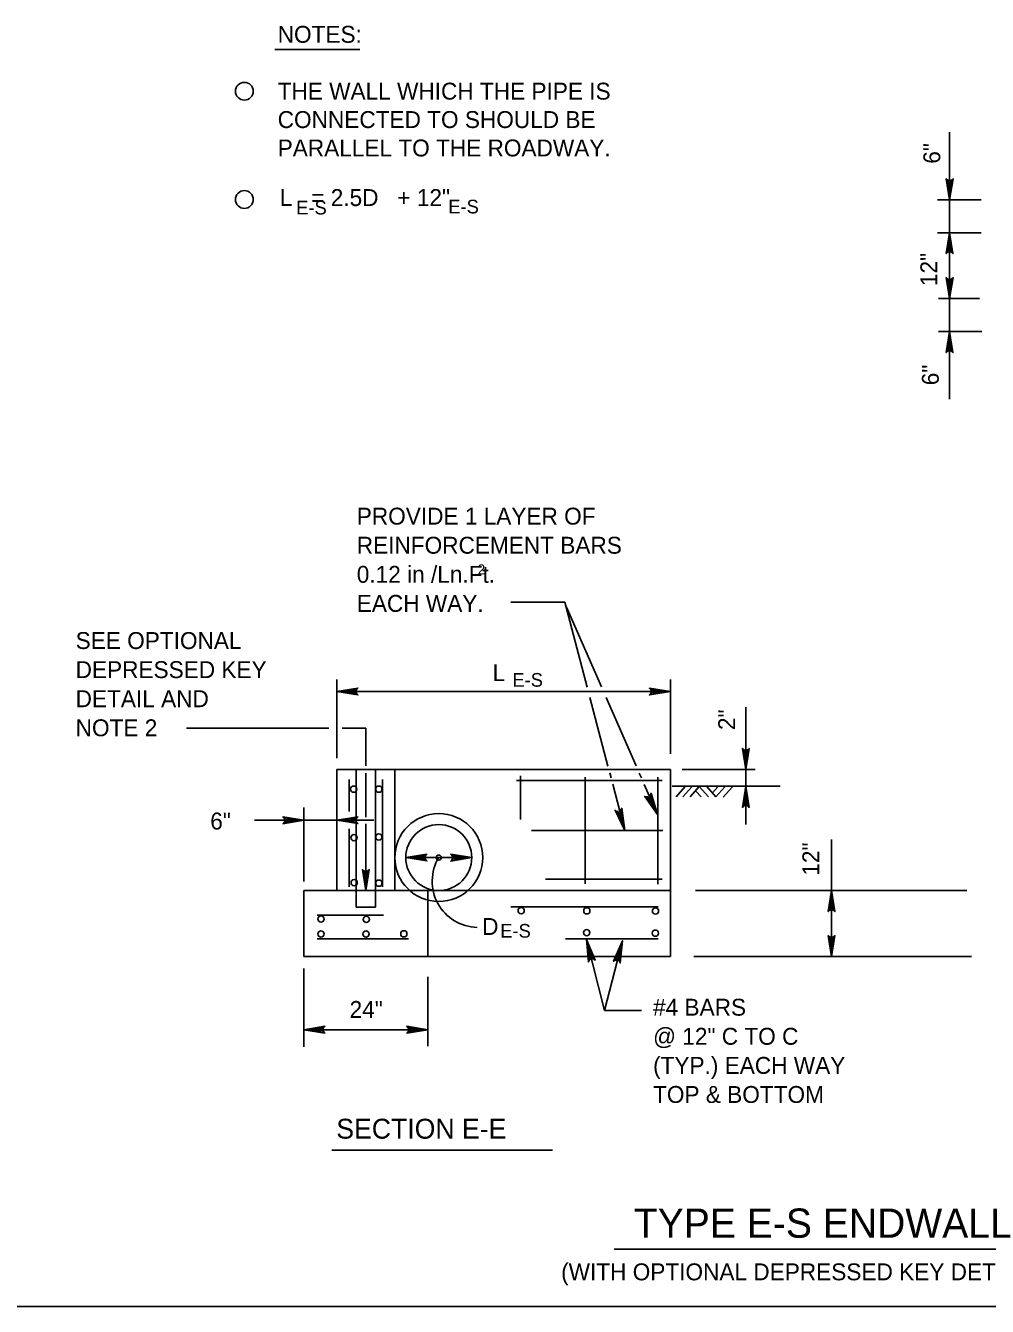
# Model space of a CAD drawing. Extents: x 638877 to 639960, y 297341 to 299123.
# Drawn here: x 639193.8 to 639364.4, y 297950.3 to 298177.5 of the extents above; entities that cross this region are included whole.
import ezdxf

# ---------------------------------------------------------------- set-up
doc = ezdxf.new("R2010")
doc.units = 0
for name, color, linetype in [('1', 7, 'Continuous'), ('2', 7, 'Continuous'), ('3', 7, 'Continuous')]:
    doc.layers.add(name, color=color, linetype=linetype)

msp = doc.modelspace()

# ---------------------------------------------------------------- linework, layer by layer
at = {"layer": '1'}
for p, q in [((639310.79, 298042.52), (639309.17, 298040.69)), ((639311.94, 298042.48), (639310.36, 298040.69)), ((639313.26, 298042.52), (639311.64, 298040.69)), ((639312.67, 298041.71), (639313.59, 298040.69)), ((639313.26, 298042.52), (639314.92, 298040.69)), ((639314.59, 298042.52), (639316.24, 298040.69)), ((639316.55, 298042.48), (639315.6, 298041.4)), ((639317.79, 298042.44), (639316.24, 298040.69)), ((639319.15, 298042.48), (639317.53, 298040.64)), ((639306.84, 298034.74), (639283.49, 298034.74)), ((638917.19, 297950.28), (639703.19, 297950.28))]:
    msp.add_line(p, q, dxfattribs=at)
for centre, radius in [((639232.58, 298165.86), 1.58), ((639232.58, 298146.66), 1.58), ((639251.98, 298042.05), 0.554), ((639256.43, 298042.05), 0.554), ((639267.07, 298029.91), 7.8), ((639252.01, 298033.46), 0.554), ((639256.43, 298033.57), 0.554), ((639267.07, 298029.91), 0.452), ((639252.06, 298025.47), 0.554), ((639256.43, 298025.37), 0.554), ((639281.69, 298020.47), 0.554), ((639293.33, 298020.46), 0.554), ((639305.51, 298020.44), 0.554), ((639246.18, 298019.01), 0.554), ((639254.21, 298018.94), 0.554), ((639246.17, 298016.35), 0.554), ((639254.16, 298016.33), 0.554), ((639260.87, 298016.38), 0.554), ((639293.31, 298016.59), 0.554), ((639305.48, 298016.49), 0.554)]:
    msp.add_circle(centre, radius, dxfattribs=at)
msp.add_arc((639274.08, 298025.7), 8.18, 149.0183, 268.6465, dxfattribs=at)
at = {"layer": '2'}
for p, q in [((639238, 298173.26), (639253.09, 298173.26)), ((639357.69, 298140.77), (639357.69, 298158.6)), ((639363.28, 298146.62), (639355.56, 298146.62)), ((639363.28, 298140.77), (639355.56, 298140.77)), ((639357.69, 298129.07), (639357.69, 298140.77)), ((639362.99, 298129.07), (639355.7, 298129.07)), ((639357.69, 298111.24), (639357.69, 298129.07)), ((639363.42, 298123.22), (639355.7, 298123.22)), ((639289.44, 298075.22), (639279.84, 298075.22)), ((639289.44, 298075.22), (639293.4, 298060.14)), ((639289.71, 298074.35), (639295.92, 298060.2)), ((639249, 298047.53), (639249, 298061.49)), ((639308.15, 298059.37), (639249, 298059.37)), ((639308.15, 298048.29), (639308.15, 298061.49)), ((639293.89, 298058.28), (639297.08, 298046.15)), ((639296.75, 298058.31), (639302.08, 298046.16)), ((639321.51, 298035.76), (639321.51, 298056.6)), ((639247.58, 298052.87), (639222.3, 298052.87)), ((639254.14, 298052.87), (639249.91, 298052.87)), ((639254.14, 298046.16), (639254.14, 298052.87)), ((639249, 298024.06), (639249, 298045.51)), ((639308.15, 298045.51), (639249, 298045.51)), ((639251.2, 298038.08), (639251.2, 298043.77)), ((639252.43, 298024.06), (639252.43, 298045.51)), ((639254.14, 298037.06), (639254.14, 298044.9)), ((639255.85, 298024.06), (639255.85, 298045.51)), ((639257.1, 298024.73), (639257.1, 298043.77)), ((639259.27, 298024.06), (639259.27, 298045.51)), ((639306.69, 298043.56), (639280.84, 298043.56)), ((639281.58, 298036.68), (639281.58, 298044.4)), ((639293.06, 298025.27), (639293.06, 298044.17)), ((639297.4, 298044.93), (639297.63, 298044.06)), ((639302.63, 298044.91), (639303.01, 298044.05)), ((639305.94, 298025.19), (639305.94, 298044.17)), ((639308.15, 298012.36), (639308.15, 298045.51)), ((639323.18, 298045.51), (639310.22, 298045.51)), ((639297.92, 298042.95), (639300.07, 298034.74)), ((639303.53, 298042.85), (639305.87, 298037.54)), ((639327.62, 298042.56), (639308.47, 298042.56)), ((639243.15, 298025.66), (639243.15, 298038.79)), ((639249, 298036.52), (639234.38, 298036.52)), ((639255.52, 298036.52), (639249, 298036.52)), ((639251.2, 298024.73), (639251.2, 298035.01)), ((639254.14, 298024.06), (639254.14, 298035.89)), ((639336.75, 298024.06), (639336.75, 298033.12)), ((639272.92, 298029.91), (639261.22, 298029.91)), ((639267.07, 298029.91), (639267.07, 298029.91)), ((639306.69, 298026.05), (639286.01, 298026.05)), ((639249, 298024.06), (639243.15, 298024.06)), ((639243.15, 298012.36), (639243.15, 298024.06)), ((639259.27, 298024.06), (639249, 298024.06)), ((639252.43, 298024.06), (639252.43, 298021.13)), ((639255.85, 298024.06), (639255.85, 298021.13)), ((639308.15, 298024.06), (639259.27, 298024.06)), ((639265.12, 298012.36), (639265.12, 298024.06)), ((639312.59, 298024.06), (639360.73, 298024.06)), ((639336.75, 298012.36), (639336.75, 298024.06)), ((639255.85, 298021.13), (639252.43, 298021.13)), ((639305.96, 298021.19), (639279.87, 298021.19)), ((639257.28, 298019.69), (639245.52, 298019.69)), ((639261.72, 298015.52), (639245.52, 298015.52)), ((639305.96, 298015.52), (639289.57, 298015.52)), ((639296.47, 298002.78), (639293.25, 298015.35)), ((639296.47, 298002.78), (639299.65, 298015.14)), ((639308.15, 298012.36), (639243.15, 298012.36)), ((639312.32, 298012.36), (639361.54, 298012.36)), ((639243.15, 297996.32), (639243.15, 298010.25)), ((639265.12, 297996.42), (639265.12, 298008.74)), ((639303.05, 298002.78), (639296.47, 298002.78)), ((639265.12, 297999.37), (639243.15, 297999.37))]:
    msp.add_line(p, q, dxfattribs=at)
for points in [[(639358.14, 298150.17), (639357.88, 298150.03), (639357.69, 298146.62), (639358.14, 298150.17), (639358.29, 298150.35), (639357.69, 298146.62), (639357.52, 298150.03), (639357.27, 298150.15), (639357.69, 298146.62), (639357.1, 298150.35), (639357.27, 298150.15)], [(639357.25, 298137.23), (639357.5, 298137.37), (639357.69, 298140.77), (639357.25, 298137.23), (639357.09, 298137.05), (639357.69, 298140.77), (639357.86, 298137.37), (639358.11, 298137.24), (639357.69, 298140.77), (639358.28, 298137.05), (639358.11, 298137.24)], [(639358.14, 298132.62), (639357.88, 298132.48), (639357.69, 298129.07), (639358.14, 298132.62), (639358.29, 298132.8), (639357.69, 298129.07), (639357.52, 298132.48), (639357.27, 298132.6), (639357.69, 298129.07), (639357.1, 298132.8), (639357.27, 298132.6)], [(639357.25, 298119.68), (639357.5, 298119.82), (639357.69, 298123.22), (639357.25, 298119.68), (639357.09, 298119.5), (639357.69, 298123.22), (639357.86, 298119.82), (639358.11, 298119.69), (639357.69, 298123.22), (639358.28, 298119.5), (639358.11, 298119.69)], [(639252.54, 298059.81), (639252.41, 298059.56), (639249, 298059.37), (639252.54, 298059.81), (639252.72, 298059.97), (639249, 298059.37), (639252.41, 298059.2), (639252.53, 298058.95), (639249, 298059.37), (639252.72, 298058.78), (639252.53, 298058.95)], [(639304.61, 298058.92), (639304.74, 298059.18), (639308.15, 298059.37), (639304.61, 298058.92), (639304.43, 298058.77), (639308.15, 298059.37), (639304.74, 298059.54), (639304.62, 298059.79), (639308.15, 298059.37), (639304.43, 298059.96), (639304.62, 298059.79)], [(639321.07, 298049.08), (639321.33, 298048.95), (639321.52, 298045.54), (639321.07, 298049.08), (639320.92, 298049.26), (639321.52, 298045.54), (639321.69, 298048.95), (639321.94, 298049.07), (639321.52, 298045.54), (639322.11, 298049.26), (639321.94, 298049.07)], [(639304.65, 298041.07), (639304.47, 298040.83), (639305.87, 298037.54), (639304.65, 298041.07), (639304.72, 298041.32), (639305.87, 298037.54), (639304.14, 298040.66), (639303.84, 298040.66), (639305.87, 298037.54), (639303.6, 298040.77), (639303.84, 298040.66)], [(639321.96, 298039), (639321.71, 298039.14), (639321.52, 298042.55), (639321.96, 298039), (639322.12, 298038.82), (639321.52, 298042.55), (639321.35, 298039.14), (639321.1, 298039.01), (639321.52, 298042.55), (639320.93, 298038.82), (639321.1, 298039.01)], [(639239.61, 298036.07), (639239.74, 298036.33), (639243.15, 298036.52), (639239.61, 298036.07), (639239.43, 298035.92), (639243.15, 298036.52), (639239.74, 298036.69), (639239.62, 298036.94), (639243.15, 298036.52), (639239.43, 298037.11), (639239.62, 298036.94)], [(639252.54, 298036.96), (639252.41, 298036.71), (639249, 298036.52), (639252.54, 298036.96), (639252.72, 298037.12), (639249, 298036.52), (639252.41, 298036.35), (639252.53, 298036.1), (639249, 298036.52), (639252.72, 298035.93), (639252.53, 298036.1)], [(639299.42, 298038.43), (639299.21, 298038.21), (639300.07, 298034.74), (639299.42, 298038.43), (639299.52, 298038.65), (639300.07, 298034.74), (639298.85, 298038.1), (639298.56, 298038.15), (639300.07, 298034.74), (639298.33, 298038.29), (639298.56, 298038.15)], [(639264.77, 298030.35), (639264.63, 298030.09), (639261.22, 298029.91), (639264.77, 298030.35), (639264.95, 298030.51), (639261.22, 298029.91), (639264.63, 298029.74), (639264.76, 298029.48), (639261.22, 298029.91), (639264.95, 298029.31), (639264.76, 298029.48)], [(639269.38, 298029.46), (639269.52, 298029.72), (639272.92, 298029.91), (639269.38, 298029.46), (639269.2, 298029.3), (639272.92, 298029.91), (639269.52, 298030.07), (639269.39, 298030.33), (639272.92, 298029.91), (639269.2, 298030.5), (639269.39, 298030.33)], [(639253.69, 298027.6), (639253.95, 298027.46), (639254.14, 298024.06), (639253.69, 298027.6), (639253.54, 298027.78), (639254.14, 298024.06), (639254.31, 298027.46), (639254.56, 298027.59), (639254.14, 298024.06), (639254.73, 298027.78), (639254.56, 298027.59)], [(639336.31, 298020.51), (639336.56, 298020.65), (639336.75, 298024.06), (639336.31, 298020.51), (639336.15, 298020.33), (639336.75, 298024.06), (639336.92, 298020.65), (639337.17, 298020.52), (639336.75, 298024.06), (639337.34, 298020.33), (639337.17, 298020.52)], [(639293.72, 298011.63), (639293.94, 298011.84), (639293.25, 298015.35), (639293.72, 298011.63), (639293.61, 298011.41), (639293.25, 298015.35), (639294.3, 298011.93), (639294.59, 298011.87), (639293.25, 298015.35), (639294.82, 298011.72), (639294.59, 298011.87)], [(639298.27, 298011.67), (639298.57, 298011.73), (639299.65, 298015.14), (639298.27, 298011.67), (639298.07, 298011.52), (639299.65, 298015.14), (639298.93, 298011.65), (639299.15, 298011.45), (639299.65, 298015.14), (639299.27, 298011.21), (639299.15, 298011.45)], [(639337.2, 298015.9), (639336.94, 298015.76), (639336.75, 298012.36), (639337.2, 298015.9), (639337.35, 298016.08), (639336.75, 298012.36), (639336.58, 298015.76), (639336.33, 298015.89), (639336.75, 298012.36), (639336.16, 298016.08), (639336.33, 298015.89)], [(639246.69, 297999.82), (639246.56, 297999.56), (639243.15, 297999.37), (639246.69, 297999.82), (639246.87, 297999.97), (639243.15, 297999.37), (639246.56, 297999.2), (639246.68, 297998.95), (639243.15, 297999.37), (639246.87, 297998.78), (639246.68, 297998.95)], [(639261.58, 297998.93), (639261.72, 297999.19), (639265.12, 297999.37), (639261.58, 297998.93), (639261.4, 297998.77), (639265.12, 297999.37), (639261.72, 297999.54), (639261.59, 297999.79), (639265.12, 297999.37), (639261.4, 297999.97), (639261.59, 297999.79)]]:
    msp.add_lwpolyline(points, dxfattribs=at)
msp.add_circle((639267.07, 298029.91), 5.85, dxfattribs=at)
at = {"layer": '3'}
for p, q in [((639248.08, 297977.97), (639287.24, 297977.97)), ((639298.18, 297960.43), (639385.48, 297960.43))]:
    msp.add_line(p, q, dxfattribs=at)

# ---------------------------------------------------------------- texts
at = {"layer": '1'}
for s, height, p in [('NOTES:', 3, (639238.49, 298174.46)), ('THE WALL WHICH THE PIPE IS', 2.9999, (639238.49, 298164.38)), ('CONNECTED TO SHOULD BE', 2.9999, (639238.49, 298159.34)), ('PARALLEL TO THE ROADWAY.', 2.9999, (639238.49, 298154.3)), ('L   = 2.5D   + 12"', 2.9999, (639238.87, 298145.5)), ('E-S', 2.43, (639241.78, 298144)), ('E-S', 2.43, (639268.76, 298144.19)), ('2', 1.8, (639273.96, 298080.13)), ('E-S', 2.43, (639280.13, 298060.22)), ('D', 3, (639274.77, 298016.18)), ('E-S', 2.43, (639277.98, 298015.7))]:
    msp.add_text(s, height=height, dxfattribs=at).set_placement(p)
at = {"layer": '2'}
msp.add_text('L', height=3, dxfattribs=at).set_placement((639276.61, 298061.21))
at = {"layer": '3'}
for s, p in [('6"', (639356.03, 298153.01)), ('12"', (639355.5, 298131.3)), ('6"', (639355.77, 298113.7)), ('2"', (639319.64, 298052.53)), ('12"', (639334.57, 298026.7))]:
    msp.add_text(s, height=3, rotation=90, dxfattribs=at).set_placement(p)
for s, height, p in [('PROVIDE 1 LAYER OF', 2.9999, (639252.52, 298088.98)), ('REINFORCEMENT BARS', 2.9999, (639252.52, 298083.82)), ('0.12 in /Ln.Ft. ', 2.9999, (639252.52, 298078.66)), ('EACH WAY.', 3, (639252.52, 298073.5)), ('SEE OPTIONAL', 2.9999, (639202.65, 298066.91)), ('DEPRESSED KEY', 2.9999, (639202.65, 298061.75)), ('DETAIL AND', 3, (639202.65, 298056.59)), ('NOTE 2', 3, (639202.65, 298051.43)), ('6"', 3, (639226.53, 298034.89)), ('#4 BARS', 3, (639305.08, 298001.86)), ('24"', 3, (639251.25, 298001.46)), ('@ 12" C TO C', 2.9999, (639305.08, 297996.7)), ('(TYP.) EACH WAY', 2.9999, (639305.08, 297991.54)), ('TOP & BOTTOM', 2.9999, (639305.08, 297986.38)), ('SECTION E-E', 3.5299, (639248.89, 297980.04)), ('TYPE E-S ENDWALL', 5.1858, (639301.66, 297962.46)), ('(WITH OPTIONAL DEPRESSED KEY DETAIL)', 2.9999, (639288.77, 297954.91))]:
    msp.add_text(s, height=height, dxfattribs=at).set_placement(p)

doc.saveas('drawing.dxf')
